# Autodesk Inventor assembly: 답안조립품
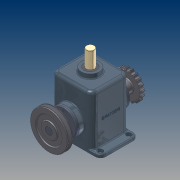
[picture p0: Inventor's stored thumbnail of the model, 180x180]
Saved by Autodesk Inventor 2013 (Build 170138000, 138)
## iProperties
Created: 2015-01
Part Number: 답안조립품
Document SubType Name: Assembly
Designer: Administrator
Author: Administrator
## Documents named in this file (15)
- C:\Users\Administrator\Desktop\350106V1010\답안조립품.iam
- C:\Users\Administrator\Desktop\350106V1010\본체.ipt
- C:\Users\Administrator\Desktop\350106V1010\M4x0.5.ipt
- C:\Users\Administrator\Desktop\350106V1010\V-벨트풀리.ipt
- C:\Users\Administrator\Desktop\350106V1010\가변스프링.ipt
- C:\Users\Administrator\Desktop\350106V1010\멈춤나사 M5x0.5.ipt
- C:\Users\Administrator\Desktop\350106V1010\멈춤링.ipt
- C:\Users\Administrator\Desktop\350106V1010\베어링 6205.ipt
- C:\Users\Administrator\Desktop\350106V1010\부시.ipt
- C:\Users\Administrator\Desktop\350106V1010\슬라이드.ipt
- C:\Users\Administrator\Desktop\350106V1010\오일실.ipt
- C:\Users\Administrator\Desktop\350106V1010\체인 스프로킷.ipt
- C:\Users\Administrator\Desktop\350106V1010\커버.ipt
- C:\Users\Administrator\Desktop\350106V1010\키 8x8.ipt
- C:\Users\Administrator\Desktop\350106V1010\편심축.ipt
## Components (9 placed, 4 different names)
1. V-벨트풀리:1 — 각도:4
2. 가변스프링:1
3. 5-체인 스프로킷:1 — 각도:5
4. M4x0.5:1 — 각도:2
5. M4x0.5:2 — 각도:3
6. M4x0.5:3
7. M4x0.5:4
8. M4x0.5:5
9. M4x0.5:6
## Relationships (4: Angle 4)
- 각도:2 [Angle]: M4x0.5:1
- 각도:3 [Angle]: M4x0.5:2
- 각도:4 [Angle]: V-벨트풀리:1
- 각도:5 [Angle]: 5-체인 스프로킷:1
